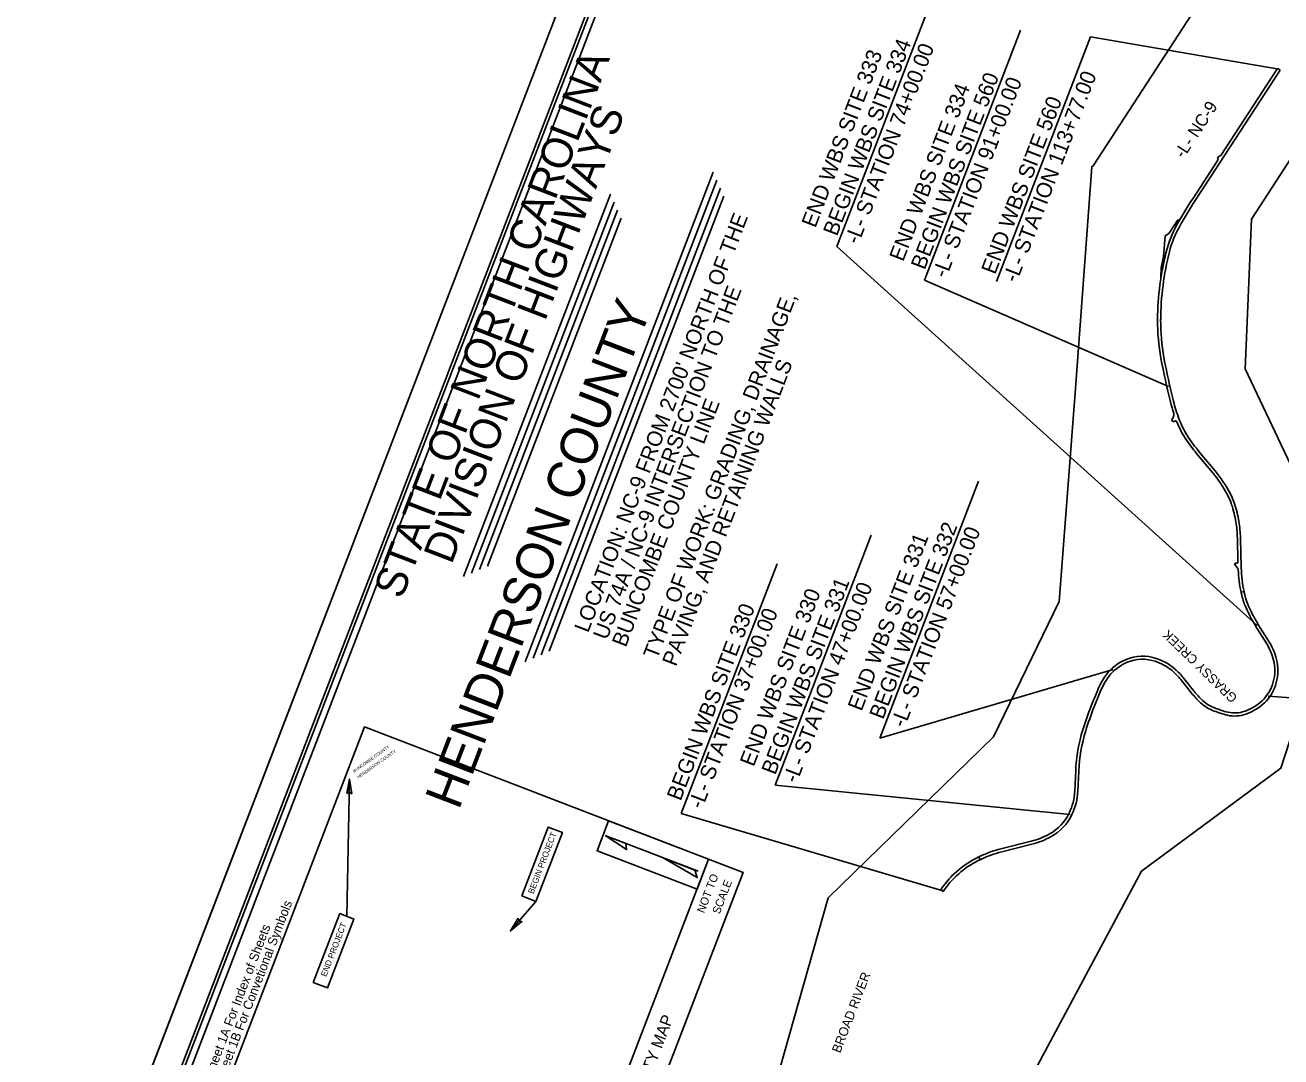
# Model space of a CAD drawing. Extents: x 1015221 to 1064345, y 619216 to 647967.
# Drawn here: x 1015221 to 1023380, y 637598 to 644303 of the extents above; entities that cross this region are included whole.
import ezdxf

# ---------------------------------------------------------------- set-up
doc = ezdxf.new("R2010")
doc.units = 0
for name, color, linetype in [('Default', 7, 'Continuous'), ('Old_Level_22', 7, 'Continuous'), ('Old_Level_32', 7, 'Continuous'), ('Prop DSN Text', 7, 'Continuous'), ('Prop RDY Alternate Text Blue', 7, 'Continuous'), ('Prop Shade Medium', 7, 'Continuous'), ('Prop Terminator CELL', 7, 'Continuous'), ('Scratch_Level_2', 7, 'Continuous'), ('Sheet Cutting Line CELL', 7, 'Continuous'), ('Sheet Data Field CELL', 7, 'Continuous'), ('Sheet North Arrow CELL', 7, 'Continuous'), ('Sheet Plot Border Inside CELL', 7, 'Continuous'), ('Sheet Plot Border Outside CELL', 7, 'Continuous'), ('Sheet Title CELL', 7, 'Continuous'), ('Sheet Title Data Points CELL', 7, 'Continuous')]:
    doc.layers.add(name, color=color, linetype=linetype)

msp = doc.modelspace()

# ---------------------------------------------------------------- linework, layer by layer
at = {"layer": 'Old_Level_22'}
for p, q in [((1017311.2, 638511.8), (1017328.3, 639403.4)), ((1018540, 638608.6), (1018373.9, 638417))]:
    msp.add_line(p, q, dxfattribs=at)
for points in [[(1018448, 638644), (1018620, 639091.7), (1018712.1, 639056.3), (1018540, 638608.6)], [(1017093.1, 638081.7), (1017265.1, 638529.5), (1017357.2, 638494.1), (1017185.2, 638046.4)]]:
    msp.add_lwpolyline(points, close=True, dxfattribs=at)
at = {"layer": 'Prop DSN Text'}
for p, q in [((1020774.2, 639670.3), (1021415.8, 641340.3)), ((1020094.3, 639364.2), (1020718.2, 640988.1)), ((1019483, 639179.6), (1020106.9, 640803.5)), ((1022289.9, 640115.5), (1020774.2, 639670.3)), ((1023297.8, 639943), (1024346.4, 639863.7)), ((1022011.1, 639172.8), (1020094.3, 639364.2)), ((1021177.5, 638679.6), (1019483, 639179.6))]:
    msp.add_line(p, q, dxfattribs=at)
for points in [[(1023225.6, 640401.1), (1020495.1, 642865.6), (1021119.1, 644489.5)], [(1022648.9, 641955), (1021065.3, 642646.5), (1021689.2, 644270.5)], [(1021532.2, 642637.7), (1022142.9, 644227.2), (1023366.7, 644016.4)]]:
    msp.add_lwpolyline(points, dxfattribs=at)
at = {"layer": 'Prop Shade Medium'}
for p, q in [((1022824.2, 643164.5), (1023375.1, 644011)), ((1023354.2, 644015.5), (1022990.6, 643456.8)), ((1023358.3, 644021.9), (1023354.2, 644015.5)), ((1023358.6, 644021.7), (1023358.3, 644021.9)), ((1023366.7, 644016.4), (1023358.6, 644021.7)), ((1023375.1, 644011), (1023366.7, 644016.4)), ((1022970.3, 643425.6), (1022807.4, 643175.4)), ((1022979.5, 643452.7), (1022968.1, 643438.9)), ((1022718.2, 643033.5), (1022711.5, 643037.4)), ((1022627.7, 642933.6), (1022617.7, 642800.6)), ((1022650.9, 642947), (1022627.7, 642933.6)), ((1022617.7, 642800.6), (1022603.1, 642726.2)), ((1022603.1, 642726.2), (1022599.6, 642665)), ((1022670.2, 641733.2), (1022686.5, 641725.5)), ((1022686.5, 641725.5), (1022687.1, 641726.7)), ((1022703.7, 641726.4), (1022703.7, 641726.3)), ((1022940.1, 641422.2), (1022856.6, 641521.7)), ((1022841.3, 641508.8), (1022924.8, 641409.4)), ((1023097.4, 640969.5), (1023101.5, 640814.1)), ((1023122.5, 640777.1), (1023117.4, 640970.1)), ((1023088.9, 640809.8), (1023078.8, 640803.2)), ((1023078.8, 640803.2), (1023083.2, 640796.5)), ((1023083.2, 640796.5), (1023099.1, 640774.7)), ((1023141.1, 640621.8), (1023121.2, 640619.1)), ((1023121.2, 640619.1), (1023141.1, 640621.8)), ((1023228.7, 640376.8), (1023288.3, 640281.5)), ((1023305.3, 640292.1), (1023245.6, 640387.5)), ((1022809.5, 639982.4), (1022751.9, 640055.3)), ((1022188, 639978.1), (1022148.4, 639879.5)), ((1022167, 639872.1), (1022206.5, 639970.7)), ((1022736.2, 640042.9), (1022793.8, 639970)), ((1022046.8, 639456.9), (1022041, 639326.9)), ((1022061, 639326), (1022066.8, 639456)), ((1021758.1, 639000), (1021561.2, 638950.4)), ((1021566.1, 638931), (1021763, 638980.6)), ((1021416.8, 638897.7), (1021425.9, 638879.9)), ((1021425.9, 638879.9), (1021416.8, 638897.7)), ((1021172.3, 638689.9), (1021177.5, 638679.6)), ((1021177.5, 638679.6), (1021185.5, 638673.9))]:
    msp.add_line(p, q, dxfattribs=at)
for points in [[(1022711.5, 643037.4), (1022657.7, 642958.3), (1022650.9, 642947)], [(1022719.9, 643032.5), (1022718.2, 643033.5)], [(1022599.6, 642665), (1022601.6, 642664.7)], [(1022684.2, 641767.2), (1022678, 641749.6), (1022670.2, 641733.2)]]:
    msp.add_lwpolyline(points, dxfattribs=at)
for centre, radius, start, end in [((1022961.9, 643431.1), 10, 326.94406, 51.72101), ((1022982.2, 643462.3), 10, 254.14752, 326.94406), ((1025349.8, 641520.8), 3033.4, 146.94406, 150.75825), ((1025349.8, 641520.8), 3013.4, 146.94406, 150.75825), ((1023301.4, 642667.6), 685.8, 150.75825, 165.79385), ((1023301.4, 642667.6), 685.8, 150.75825, 165.79385), ((1023301.4, 642667.6), 665.8, 150.75825, 165.79385), ((1025349.8, 641520.8), 3033.4, 150.10872, 150.75825), ((1024461, 642374), 1882, 165.79385, 179.51674), ((1024461, 642374), 1862, 165.79385, 179.51674), ((1024461, 642374), 1882, 165.79385, 171.1151), ((1023905.1, 642378.7), 1326.1, 179.51674, 190.40448), ((1023905.1, 642378.7), 1306.1, 179.51674, 190.40448), ((1027003, 642947.5), 4475.8, 190.40448, 194.13293), ((1027003, 642947.5), 4455.8, 190.40448, 194.13293), ((1023714, 642119.4), 1084.1, 194.13293, 198.23721), ((1023714, 642119.4), 1064.1, 194.13293, 200.53267), ((1022665.4, 641773.8), 20, 340.68335, 18.23721), ((1022695.3, 641723.1), 9, 21.77194, 156.43622), ((1023288.1, 641959.9), 629.4, 201.78316, 214.3994), ((1023288.1, 641959.9), 609.4, 200.53267, 214.3994), ((1023780.6, 642297.1), 1226.2, 214.3994, 220.00236), ((1023780.6, 642297.1), 1206.2, 214.3994, 220.00236), ((1022167.9, 640774.2), 988.1, 30.35075, 40.00236), ((1022167.9, 640774.2), 1008.1, 30.35075, 40.00236), ((1022614.5, 641035.7), 470.5, 18.65707, 30.35075), ((1022614.5, 641035.7), 490.5, 18.65707, 30.35075), ((1022417.8, 640969.3), 698.2, 8.97292, 18.65707), ((1022417.8, 640969.3), 678.2, 8.97292, 18.65707), ((1022281.1, 640947.7), 816.6, 1.53224, 8.97292), ((1022281.1, 640947.7), 836.6, 1.53224, 8.97292), ((1023094.5, 640813.9), 7, 216.49724, 1.53224), ((1023083, 640762.9), 20, 2.38019, 36.15683), ((1023970.9, 640799.8), 868.7, 182.38019, 192.0019), ((1023970.9, 640799.8), 848.7, 181.53224, 192.10634), ((1023970.9, 640799.8), 868.7, 192.0019, 193.71972), ((1023970.9, 640799.8), 848.7, 192.10634, 193.71972), ((1023543.7, 640695.5), 428.9, 193.71972, 204.13512), ((1023543.7, 640695.5), 408.9, 193.71972, 204.13512), ((1024228.9, 641002.5), 1179.8, 204.13512, 212.0264), ((1024228.9, 641002.5), 1159.8, 204.13512, 212.0264), ((1022986.2, 640092.6), 376.4, 10.94943, 32.0264), ((1022986.2, 640092.6), 356.4, 10.94943, 32.0264), ((1022499.9, 639887.7), 319.8, 117.79178, 146.06711), ((1022499.9, 639887.7), 299.8, 117.79178, 146.06711), ((1022480.2, 639925.1), 277.5, 75.89747, 117.79178), ((1022480.2, 639925.1), 257.5, 75.89747, 117.79178), ((1022463, 639856.6), 328.1, 47.0981, 75.89747), ((1022463, 639856.6), 348.1, 47.0981, 75.89747), ((1023067.6, 640108.3), 273.4, 310.51343, 10.94943), ((1023067.6, 640108.3), 293.4, 310.51343, 10.94943), ((1022627.1, 639802.1), 473.1, 146.06711, 158.15553), ((1022627.1, 639802.1), 453.1, 146.06711, 158.15553), ((1022360.5, 639746.3), 478.7, 38.28466, 47.0981), ((1022360.5, 639746.3), 498.7, 38.28466, 47.0981), ((1023352.4, 640410.9), 711.7, 218.28466, 224.94478), ((1023352.4, 640410.9), 691.7, 218.28466, 224.94478), ((1023034.5, 640093.6), 262.5, 224.94478, 248.08344), ((1023034.5, 640093.6), 242.5, 224.94478, 248.08344), ((1023054.2, 640124.1), 294.1, 285.24327, 310.51343), ((1023054.2, 640124.1), 314.1, 285.24327, 310.51343), ((1024031.2, 639124.8), 2028.5, 158.15553, 162.84813), ((1024031.2, 639124.8), 2008.5, 158.15553, 162.84813), ((1023246.7, 640621), 831, 248.08344, 254.14272), ((1023246.7, 640621), 811, 248.08344, 254.14272), ((1023079.3, 640031.8), 218.5, 254.14272, 285.24327), ((1023079.3, 640031.8), 198.5, 254.14272, 285.24327), ((1023107.7, 639409.8), 1061.9, 162.84813, 177.45749), ((1023107.7, 639409.8), 1041.9, 162.84813, 177.45749), ((1021670.1, 639343.3), 371.3, 334.12263, 357.45749), ((1021670.1, 639343.3), 391.3, 334.12263, 357.45749), ((1021728.7, 639314.9), 306.2, 299.08312, 334.12263), ((1021728.7, 639314.9), 326.2, 299.08312, 334.12263), ((1021637.5, 639478.9), 493.8, 284.13604, 299.08312), ((1021637.5, 639478.9), 513.8, 284.13604, 299.08312), ((1021743.1, 638228.3), 744.7, 104.13604, 115.98541), ((1021743.1, 638228.3), 724.7, 104.13604, 115.95706), ((1021666.3, 638360.4), 591.9, 120.13891, 135.33979), ((1021666.3, 638360.4), 571.9, 120.13891, 135.33979), ((1021743.1, 638228.3), 744.7, 115.98541, 120.13891), ((1021743.1, 638228.3), 724.7, 115.95706, 120.13891), ((1021756.1, 638271.7), 718.1, 135.33979, 144.38653), ((1021756.1, 638271.7), 698.1, 135.33979, 144.81862)]:
    msp.add_arc(centre, radius, start, end, dxfattribs=at)
at = {"layer": 'Prop Terminator CELL'}
for points in [[(1017310.3, 639309.6), (1017328.3, 639403.4), (1017343.2, 639308.4), (1017326.7, 639320.8)], [(1018423.3, 638498.8), (1018373.9, 638417), (1018448.6, 638477.6), (1018428, 638479.5)]]:
    msp.add_lwpolyline(points, close=True, dxfattribs=at)
at = {"layer": 'Scratch_Level_2'}
msp.add_lwpolyline([(1020895.4, 635853.8), (1022473.8, 638805.7), (1023379.2, 639473.6), (1023843, 640900.1), (1023637.3, 641036.3), (1023148.3, 642068.8), (1023188.2, 643043.1), (1024411.5, 644926.1), (1023531, 645498.1), (1022160.6, 643388.7), (1022151.2, 643382.8), (1022046.3, 641942.6), (1021939, 640556.9), (1021513.5, 639679.1), (1020439.2, 638632.2), (1020121.4, 637513.2), (1020059.5, 637223.8), (1019861.3, 636035.8)], close=True, dxfattribs=at)
at = {"layer": 'Sheet Cutting Line CELL'}
msp.add_line((1015220.5, 635391.3), (1020052.2, 647967.1), dxfattribs=at)
at = {"layer": 'Sheet North Arrow CELL'}
msp.add_line((1019593.1, 638804.7), (1018989.1, 639036.7), dxfattribs=at)
for points in [[(1018989.1, 639036.7), (1019127.9, 638945.1), (1019123.9, 638984.9)], [(1019367.4, 638891.4), (1019588.2, 638763.2), (1019572.9, 638812.4)]]:
    msp.add_lwpolyline(points, close=True, dxfattribs=at)
at = {"layer": 'Sheet Plot Border Inside CELL'}
msp.add_lwpolyline([(1023304.8, 632396.8), (1028086.2, 644841.8), (1020206.9, 647869.1), (1015425.5, 635424)], close=True, dxfattribs=at)
at = {"layer": 'Sheet Plot Border Outside CELL'}
msp.add_lwpolyline([(1020052.2, 647967.1), (1015220.5, 635391.3), (1023435, 632235.3), (1028266.7, 644811.1)], close=True, dxfattribs=at)
at = {"layer": 'Sheet Title CELL'}
for p, q in [((1018470, 640165.5), (1019692.4, 643346.8)), ((1018521.7, 640188.5), (1019715.4, 643295.1)), ((1018573.5, 640211.5), (1019738.3, 643243.4)), ((1018069.3, 640719.3), (1019023.9, 643204.2)), ((1018120.9, 640742.3), (1019047, 643152.5)), ((1018625.1, 640234.5), (1019761.4, 643191.7)), ((1018172.7, 640765.3), (1019069.9, 643100.9)), ((1018224.3, 640788.3), (1019092.9, 643049.2))]:
    msp.add_line(p, q, dxfattribs=at)
for points in [[(1020161.5, 647693.8), (1015914.9, 636641.4)], [(1020184.4, 647642.1), (1016110.2, 637037.9)]]:
    msp.add_lwpolyline(points, dxfattribs=at)
for points in [[(1016474.2, 637264.3), (1017426.2, 639742.1), (1019661.5, 638883.2), (1018709.6, 636405.5)], [(1019586.6, 638688.1), (1019661.5, 638883.2), (1019011.4, 639133), (1018936.5, 638937.9)], [(1019661.5, 638883.2), (1018709.6, 636405.5), (1018933.6, 636319.4), (1019885.6, 638797.2)]]:
    msp.add_lwpolyline(points, close=True, dxfattribs=at)
at = {"layer": 'Sheet Title Data Points CELL'}
for p, q in [((1019724.8, 642551), (1019724.8, 642551)), ((1018974.4, 641810.5), (1018974.4, 641810.5))]:
    msp.add_line(p, q, dxfattribs=at)

# ---------------------------------------------------------------- texts
at = {"layer": 'Default'}
for s, p in [('BUNCOMBE COUNTY', (1017359.2, 639443.8)), ('HENDERSON COUNTY', (1017387.3, 639405.8))]:
    msp.add_text(s, height=20, rotation=35.50642, dxfattribs=at).set_placement(p)
at = {"layer": 'Old_Level_22'}
for s, p in [('BEGIN PROJECT', (1018523.3, 638654.5)), ('END PROJECT', (1017177.5, 638115.9))]:
    msp.add_text(s, height=39.216, rotation=68.98302, dxfattribs=at).set_placement(p)
at = {"layer": 'Old_Level_32'}
for s, height, p in [('NOT TO ', 52.29, (1019632.3, 638528.8)), ('SCALE', 52.29, (1019732.7, 638522.1)), ('VICINITY MAP', 76.44, (1019191, 637217.3))]:
    msp.add_text(s, height=height, rotation=68.98302, dxfattribs=at).set_placement(p)
at = {"layer": 'Prop DSN Text'}
for s, height, rotation, p in [('BEGIN WBS SITE 334', 100, 68.98302, (1020495.6, 642927)), ('END WBS SITE 333', 100, 68.98302, (1020355.5, 642980.8)), ('-L- STATION 74+00.00', 100, 68.98302, (1020635.6, 642873.2)), ('BEGIN WBS SITE 560', 100, 68.98302, (1021065.7, 642708)), ('-L- STATION 91+00.00', 100, 68.98302, (1021205.7, 642654.2)), ('-L- STATION 113+77.00', 100, 68.98302, (1021663.1, 642624)), ('END WBS SITE 334', 100, 68.98302, (1020925.7, 642761.8)), ('END WBS SITE 560', 100, 68.98302, (1021523.1, 642677.8)), ('-L- NC-9', 80, 56.81533, (1022748.2, 643432.3)), ('BEGIN WBS SITE 332', 100, 68.98302, (1020795.5, 639786.1)), ('-L- STATION 57+00.00', 100, 68.98302, (1020935.5, 639732.3)), ('END WBS SITE 331', 100, 68.98302, (1020655.5, 639839.9)), ('END WBS SITE 330', 100, 68.98302, (1019954.7, 639479.4)), ('BEGIN WBS SITE 331', 100, 68.98302, (1020094.7, 639425.6)), ('-L- STATION 47+00.00', 100, 68.98302, (1020234.7, 639371.8)), ('BEGIN WBS SITE 330', 100, 68.98302, (1019479.8, 639256.7)), ('-L- STATION 37+00.00', 100, 68.98302, (1019619.8, 639202.9))]:
    msp.add_text(s, height=height, rotation=rotation, dxfattribs=at).set_placement(p)
at = {"layer": 'Prop RDY Alternate Text Blue'}
for s, rotation, p in [('GRASSY CREEK', 135.76292, (1023102.1, 639936.8)), ('BROAD RIVER', 68.98302, (1020516.4, 637619))]:
    msp.add_text(s, height=60, rotation=rotation, dxfattribs=at).set_placement(p)
at = {"layer": 'Sheet Data Field CELL'}
msp.add_text('      HENDERSON COUNTY       ', height=240, rotation=68.98302, dxfattribs=at).set_placement((1017846.3, 638697.4))
at = {"layer": 'Sheet Title CELL'}
for s, height, p in [('STATE OF NORTH CAROLINA', 199.999, (1017668.2, 640566.6)), ('DIVISION OF HIGHWAYS', 199.999, (1017990.9, 640793.1)), ("LOCATION: NC-9 FROM 2700' NORTH OF THE ", 100.001, (1018878.9, 640349.7)), ('US 74A / NC-9 INTERSECTION TO THE ', 100.001, (1019001.3, 640302.6)), ('TYPE OF WORK: GRADING, DRAINAGE, ', 100.001, (1019327.4, 640177.3)), ('PAVING, AND RETAINING WALLS', 100.001, (1019449.8, 640130.3)), ('BUNCOMBE COUNTY LINE', 100.001, (1019123.7, 640255.6)), ('See Sheet 1B For Convetional Symbols', 60, (1016450.7, 637281.4)), ('See Sheet 1A For Index of Sheets', 60, (1016379.7, 637308.6))]:
    msp.add_text(s, height=height, rotation=68.98302, dxfattribs=at).set_placement(p)

doc.saveas('drawing.dxf')
